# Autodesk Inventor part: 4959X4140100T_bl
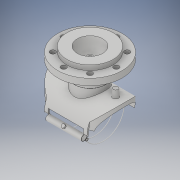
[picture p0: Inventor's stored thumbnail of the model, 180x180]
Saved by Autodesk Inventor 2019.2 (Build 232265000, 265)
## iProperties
Created: 2020-06
Part Number: 4959X4140100T_bl
Material: Generic
Description: Plasson Flanged Branch Saddle 140x100
Document SubType Name: Modeling
Designer: KIM
Density: 1 g/cm^3
Appearance: Default
Author: KIM
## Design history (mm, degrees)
derived "4959X4.ipt"
feature "Solid1::4959X4.ipt" dims "ScaleForDerivedMember" = 10
feature "Solid2::4959X4.ipt" dims "ScaleForDerivedMember" = 10
tag "TaggingFeature1"
body "Solid1"
body "Solid2"
other parameters: "d0" = 242 [user parameter], "d4" = 118 [user parameter], "d7" = 87 [user parameter], "d10" = 0.5 [user parameter], "d11" = 1 [user parameter], "d12" = 29.5 [user parameter], "d13" = 16 [user parameter], "d14" = 8 [user parameter], "d16" = 10 deg [user parameter], "d17" = 10 deg [user parameter], "d19" = 0 [user parameter], "d23" = 0 [user parameter], "d26" = 0 [user parameter], "d27" = 145.2 [user parameter], "d28" = 0 [user parameter], "d29" = 121 [user parameter], "d30" = 0 [user parameter], "d31" = 1 [user parameter], "d32" = 1 [user parameter], "d33" = 19.2 [user parameter], "d34" = 9.6 [user parameter], "d35" = 45 deg [user parameter], "d36" = 121 [user parameter], "d37" = 0 [user parameter], "d38" = 5 [user parameter], "d39" = 85 deg [user parameter], "d40" = 29.5 [user parameter], "d41" = 16 [user parameter], "d42" = 88 [user parameter], "d49" = 3 [user parameter], "d50" = 6 [user parameter], "d51" = 5 [user parameter], "d54" = 0 [user parameter], "d57" = 35 deg [user parameter], "d60" = 15.125 [user parameter], "d61" = 1 [user parameter], "d62" = 90 deg [user parameter], "d63" = 2 [user parameter], "d64" = 0 [user parameter], "d65" = 0 [user parameter], "d68" = 30.25 [user parameter], "d70" = 0.57711 [user parameter], "d71" = 10 deg [user parameter], "d73" = 4.55 [user parameter], "d75" = 22 [user parameter], "d77" = 89.25 [user parameter], "d78" = 105 [user parameter], "d79" = 158 [user parameter], "d80" = 1 [user parameter], "d81" = 104.4 [user parameter], "d82" = 121.8 [user parameter], "d83" = 1 [user parameter], "d84" = 16.5 [user parameter], "d87" = 18 [user parameter], "d95" = 360 deg [user parameter], "d_h" = 158 [user parameter], "B" = 186 [user parameter], "L" = 242 [user parameter], "LS" = 105 [user parameter], "H1" = 118 [user parameter], "Dt" = 16 [user parameter], "di" = 87 [user parameter], "s_" = 18 [user parameter], "t" = 22 [user parameter], "d72" = 13 [user parameter]
